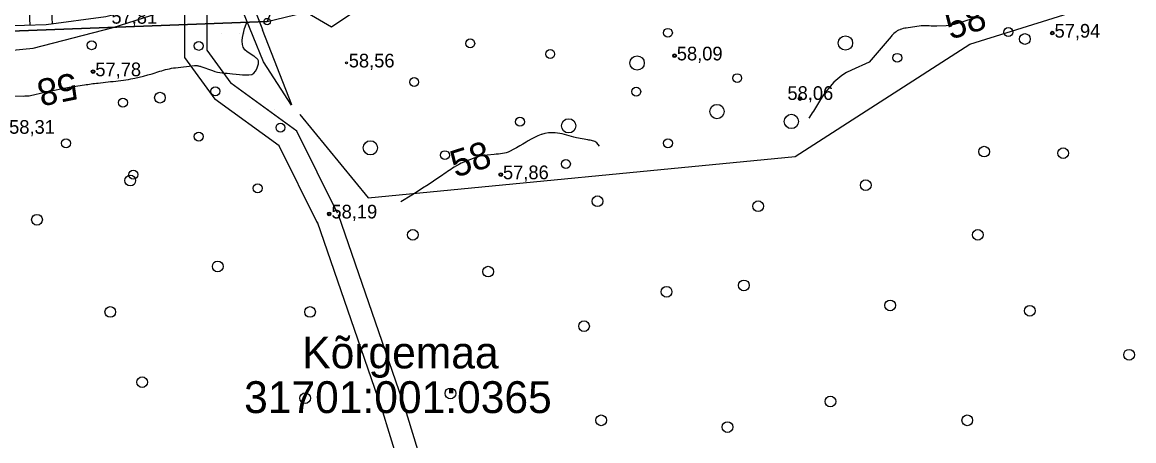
# Model space of a CAD drawing. Extents: x 532503 to 539665, y 6557663 to 6561526.
# Drawn here: x 535060.8 to 535259.9, y 6559424.7 to 6559499.7 of the extents above; entities that cross this region are included whole.
import ezdxf

# ---------------------------------------------------------------- set-up
doc = ezdxf.new("R2010")
doc.units = 0
for name, color, linetype in [('Default', 7, 'Continuous'), ('HALJASTUS', 7, 'Continuous'), ('HORISONTAAL-EH2000', 7, 'Continuous'), ('kataster', 7, 'Continuous'), ('KORGUS-EH2000', 7, 'Continuous'), ('PIIRIMLEITUD', 7, 'Continuous'), ('RELJEEF', 7, 'Continuous'), ('RELJEEF 1', 7, 'Continuous'), ('TEE', 7, 'Continuous'), ('TM_aktiivne', 7, 'Continuous')]:
    doc.layers.add(name, color=color, linetype=linetype)

# ---------------------------------------------------------------- blocks, each defined once
blk = doc.blocks.new('LONOOR')
at = {"layer": 'HALJASTUS'}
blk.add_circle((0, 0), 0.6, dxfattribs=at)
blk = doc.blocks.new('POINT_DISPLAY')
at = {"layer": 'Default'}
blk.add_line((0, 0), (0, 0), dxfattribs=at)

msp = doc.modelspace()

# ---------------------------------------------------------------- linework, layer by layer
at = {"layer": 'HALJASTUS'}
msp.add_lwpolyline([(535110.49, 6559483.15), (535110.49, 6559483.15), (535122.71, 6559468.22), (535199.25, 6559475.6), (535230.51, 6559495.77), (535263.23, 6559506), (535276.96, 6559503.95), (535294.2, 6559495.48)], dxfattribs=at)
for centre, radius in [((535176.42, 6559497.78), 0.8), ((535176.42, 6559497.78), 0.8), ((535237.41, 6559497.91), 0.8), ((535237.41, 6559497.91), 0.8), ((535073.19, 6559495.56), 0.8), ((535073.19, 6559495.56), 0.8), ((535092.38, 6559495.44), 0.8), ((535092.38, 6559495.44), 0.8), ((535141.01, 6559495.88), 0.8), ((535141.01, 6559495.88), 0.8), ((535208.23, 6559495.95), 1.28), ((535155.34, 6559493.98), 0.8), ((535155.34, 6559493.98), 0.8), ((535217.51, 6559493.3), 0.8), ((535217.51, 6559493.3), 0.8), ((535170.91, 6559492.37), 1.28), ((535188.84, 6559489.66), 0.8), ((535188.84, 6559489.66), 0.8), ((535095.36, 6559487.31), 0.8), ((535095.36, 6559487.31), 0.8), ((535130.97, 6559488.96), 0.8), ((535130.97, 6559488.96), 0.8), ((535170.75, 6559487.25), 0.8), ((535170.75, 6559487.25), 0.8), ((535078.79, 6559485.28), 0.8), ((535078.79, 6559485.28), 0.8), ((535185.22, 6559483.68), 1.28), ((535149.93, 6559481.85), 0.8), ((535149.93, 6559481.85), 0.8), ((535158.64, 6559481.12), 1.28), ((535198.55, 6559481.9), 1.28), ((535092.38, 6559479.2), 0.8), ((535092.38, 6559479.2), 0.8), ((535107.02, 6559480.8), 0.8), ((535107.02, 6559480.8), 0.8), ((535068.61, 6559477.99), 0.8), ((535068.61, 6559477.99), 0.8), ((535123.13, 6559477.18), 1.28), ((535176.44, 6559478), 0.8), ((535176.44, 6559478), 0.8), ((535136.48, 6559475.87), 0.8), ((535136.48, 6559475.87), 0.8), ((535158.15, 6559474.29), 0.8), ((535158.15, 6559474.29), 0.8), ((535080.66, 6559472.38), 0.8), ((535102.93, 6559469.93), 0.8), ((535102.93, 6559469.93), 0.8)]:
    msp.add_circle(centre, radius, dxfattribs=at)
at = {"layer": 'HORISONTAAL-EH2000'}
for points in [[(535069.14, 6559488.04), (535071.89, 6559488.45), (535072.19, 6559488.5), (535072.5, 6559488.55), (535072.81, 6559488.59), (535073.11, 6559488.64), (535073.42, 6559488.68), (535073.73, 6559488.72), (535074.04, 6559488.76), (535074.35, 6559488.79), (535076.58, 6559489.03), (535077.04, 6559489.07), (535077.5, 6559489.12), (535077.96, 6559489.18), (535078.42, 6559489.23), (535078.87, 6559489.29), (535079.33, 6559489.35), (535079.78, 6559489.43), (535080.24, 6559489.52), (535080.92, 6559489.66), (535081.71, 6559489.83), (535082.49, 6559490.02), (535083.27, 6559490.23), (535084.04, 6559490.46), (535085.4, 6559490.88), (535085.74, 6559490.98), (535086.09, 6559491.08), (535086.44, 6559491.18), (535086.8, 6559491.27), (535087.15, 6559491.35), (535087.5, 6559491.42), (535087.86, 6559491.48), (535088.22, 6559491.53), (535091.64, 6559491.9), (535091.78, 6559491.91), (535091.93, 6559491.91), (535092.07, 6559491.9), (535092.21, 6559491.88), (535092.36, 6559491.86), (535092.5, 6559491.82), (535092.64, 6559491.78), (535092.77, 6559491.74), (535094.84, 6559491), (535095.27, 6559490.87), (535095.71, 6559490.75), (535096.15, 6559490.68), (535096.6, 6559490.62), (535097.05, 6559490.58), (535097.5, 6559490.54), (535097.95, 6559490.49), (535098.4, 6559490.45), (535099.11, 6559490.37), (535099.68, 6559490.31), (535100.24, 6559490.27), (535100.8, 6559490.25), (535101.37, 6559490.23), (535101.86, 6559490.34), (535102.27, 6559490.54), (535102.57, 6559490.88), (535102.8, 6559491.32), (535103.06, 6559492.25), (535103.09, 6559492.37), (535103.1, 6559492.5), (535103.09, 6559492.63), (535103.07, 6559492.75), (535103.03, 6559492.87), (535102.97, 6559492.98), (535102.9, 6559493.08), (535102.81, 6559493.17), (535102.75, 6559493.22), (535102.62, 6559493.32), (535102.49, 6559493.42), (535102.36, 6559493.52), (535102.22, 6559493.61), (535101.07, 6559494.36), (535100.65, 6559494.75), (535100.34, 6559495.19), (535100.19, 6559495.7), (535100.14, 6559496.27), (535100.15, 6559496.38), (535100.22, 6559496.93), (535100.31, 6559497.49), (535100.44, 6559498.03), (535100.6, 6559498.57), (535101.03, 6559499.82)], [(535231.73, 6559500.52), (535227.73, 6559499.25), (535227.49, 6559499.2), (535226.87, 6559499.11), (535226.26, 6559499.05), (535224.63, 6559498.96), (535224.27, 6559498.95), (535223.92, 6559498.95), (535223.56, 6559498.97), (535223.21, 6559499.01), (535222.85, 6559499.04), (535222.5, 6559499.05), (535222.15, 6559499.04), (535221.79, 6559499), (535219.13, 6559498.64), (535218.85, 6559498.59), (535218.57, 6559498.53), (535218.3, 6559498.45), (535218.03, 6559498.35), (535217.97, 6559498.33), (535217.74, 6559498.23), (535217.52, 6559498.11), (535217.31, 6559497.97), (535217.11, 6559497.82), (535216.93, 6559497.66), (535216.74, 6559497.48), (535216.57, 6559497.3), (535216.4, 6559497.12), (535212.5, 6559492.5), (535209.29, 6559491.1), (535208.43, 6559490.66), (535207.61, 6559490.16), (535206.86, 6559489.56), (535206.15, 6559488.91), (535205.49, 6559488.18), (535204.88, 6559487.43), (535204.31, 6559486.65), (535203.78, 6559485.83), (535202.89, 6559484.37), (535202.69, 6559484.05), (535202.49, 6559483.74), (535202.29, 6559483.43), (535202.09, 6559483.12), (535201.67, 6559482.5)], [(535057.94, 6559486.49), (535060.93, 6559486.46), (535061.2, 6559486.47), (535061.46, 6559486.48), (535061.72, 6559486.5), (535061.98, 6559486.52), (535062.24, 6559486.56), (535062.5, 6559486.6), (535062.75, 6559486.65), (535063.01, 6559486.71), (535065.02, 6559487.2), (535069.14, 6559488.04)], [(535164.17, 6559477.5), (535163.67, 6559478.05), (535163.51, 6559478.19), (535163.34, 6559478.31), (535163.14, 6559478.4), (535162.94, 6559478.46), (535162.72, 6559478.5), (535162.5, 6559478.54), (535162.28, 6559478.58), (535162.06, 6559478.62), (535160.03, 6559479), (535159.6, 6559479.09), (535159.17, 6559479.19), (535158.75, 6559479.31), (535158.33, 6559479.44), (535157.91, 6559479.56), (535157.49, 6559479.67), (535157.06, 6559479.74), (535156.63, 6559479.81), (535156.25, 6559479.85), (535155.62, 6559479.88), (535155.01, 6559479.85), (535154.4, 6559479.74), (535153.8, 6559479.57), (535153.75, 6559479.56), (535153.13, 6559479.32), (535152.53, 6559479.05), (535151.95, 6559478.75), (535151.38, 6559478.42), (535151.04, 6559478.21), (535150.46, 6559477.86), (535149.88, 6559477.52), (535149.29, 6559477.19), (535148.7, 6559476.87), (535148.14, 6559476.58), (535147.82, 6559476.43), (535147.48, 6559476.3), (535147.13, 6559476.21), (535146.78, 6559476.15), (535146.42, 6559476.11), (535146.06, 6559476.07), (535145.69, 6559476.03), (535145.33, 6559476), (535144.06, 6559475.89), (535143.29, 6559475.79), (535142.53, 6559475.65), (535142.41, 6559475.62)], [(535142.41, 6559475.62), (535139.41, 6559474.44), (535139.08, 6559474.26), (535138.55, 6559473.96), (535138.11, 6559473.7), (535137.81, 6559473.51), (535137.51, 6559473.32), (535137.22, 6559473.12), (535136.93, 6559472.92), (535136.64, 6559472.71), (535136.35, 6559472.51), (535136.06, 6559472.31), (535135.77, 6559472.11), (535134.41, 6559471.2), (535133.45, 6559470.57), (535132.49, 6559469.94), (535131.52, 6559469.32), (535130.55, 6559468.71), (535128.61, 6559467.5)]]:
    msp.add_lwpolyline(points, dxfattribs=at)
at = {"layer": 'kataster'}
for points in [[(534957.01, 6559532.73), (534874.65, 6559775.26), (534941.15, 6559817.08), (535181.52, 6559689.04), (535104.64, 6559499.79), (534969.93, 6559494.75)], [(534969.93, 6559494.75), (535104.64, 6559499.79), (535276.49, 6559541.25), (535318.85, 6559280.76), (535338.01, 6559156.08), (535319.42, 6559157.12), (535277.91, 6559164.57), (535224.85, 6559174.15), (535170.96, 6559181.67), (535149.92, 6559184.62), (535125.2, 6559187.34), (535093.5, 6559192.16), (535054.28, 6559206.76)]]:
    msp.add_lwpolyline(points, close=True, dxfattribs=at)
at = {"layer": 'KORGUS-EH2000'}
for centre, radius in [((535245.29, 6559497.73), 0.32), ((535245.29, 6559497.73), 0.2), ((535245.29, 6559497.73), 0.2), ((535177.62, 6559493.67), 0.32), ((535177.62, 6559493.67), 0.2), ((535118.85, 6559492.4), 0.2), ((535118.85, 6559492.4), 0.2), ((535073.45, 6559490.83), 0.32), ((535073.45, 6559490.83), 0.2), ((535200.1, 6559486), 0.32), ((535200.1, 6559486), 0.2), ((535146.48, 6559472.39), 0.32), ((535146.48, 6559472.39), 0.2), ((535146.48, 6559472.39), 0.2), ((535115.75, 6559465.35), 0.32), ((535115.75, 6559465.35), 0.2)]:
    msp.add_circle(centre, radius, dxfattribs=at)
at = {"layer": 'PIIRIMLEITUD'}
msp.add_circle((535104.64, 6559499.79), 0.57, dxfattribs=at)
at = {"layer": 'RELJEEF'}
for p, q in [((535061.73, 6559506.63), (535062.14, 6559499.1)), ((535065.73, 6559506.85), (535066.13, 6559499.33))]:
    msp.add_line(p, q, dxfattribs=at)
for points in [[(535109.02, 6559484.82), (535103.98, 6559492.59), (535100.29, 6559501.64), (535100.5, 6559504.84), (535103.25, 6559507.91), (535105.72, 6559508.12), (535110.74, 6559506.58), (535115.7, 6559504.44), (535119.85, 6559506.31), (535124.94, 6559512.6)], [(535109.02, 6559484.82), (535103.98, 6559492.59), (535100.29, 6559501.64), (535100.5, 6559504.84), (535103.25, 6559507.91), (535105.72, 6559508.12), (535110.74, 6559506.58), (535115.7, 6559504.44), (535119.85, 6559506.31), (535124.94, 6559512.6)], [(535114.09, 6559509.72), (535109.81, 6559508.21), (535101.81, 6559506.5), (535087.91, 6559503.76), (535075.73, 6559500.64), (535065.04, 6559499.19), (535049.48, 6559498.72), (535035.15, 6559499.38), (535025.73, 6559500.28), (535016.96, 6559498.58), (535002.85, 6559496.63)], [(535125.39, 6559505.04), (535116.17, 6559498.77), (535105.71, 6559504.91), (535102.67, 6559501.25), (535103.79, 6559498.35)], [(535125.39, 6559505.04), (535116.17, 6559498.77), (535105.71, 6559504.91), (535102.67, 6559501.25), (535103.79, 6559498.35)], [(535103.76, 6559498.4), (535108.99, 6559484.93)], [(535103.76, 6559498.4), (535108.99, 6559484.93)]]:
    msp.add_lwpolyline(points, dxfattribs=at)
at = {"layer": 'RELJEEF 1'}
for points in [[(535109.02, 6559484.82), (535103.98, 6559492.59), (535100.29, 6559501.64), (535100.5, 6559504.84), (535103.25, 6559507.91), (535105.72, 6559508.12), (535110.74, 6559506.58), (535115.7, 6559504.44), (535119.85, 6559506.31), (535124.94, 6559512.6)], [(535125.39, 6559505.04), (535116.17, 6559498.77), (535105.71, 6559504.91), (535102.67, 6559501.25), (535103.79, 6559498.35)], [(535055.91, 6559494.38), (535062.74, 6559495.05), (535077.04, 6559498.73), (535085.08, 6559501.31), (535095.91, 6559503.08), (535100.29, 6559501.64)], [(535103.76, 6559498.4), (535108.99, 6559484.93)]]:
    msp.add_lwpolyline(points, dxfattribs=at)
at = {"layer": 'TEE'}
for p, q in [((535089.8, 6559503.31), (535089.8, 6559493.34)), ((535093.8, 6559503.72), (535093.8, 6559494.66)), ((535093.8, 6559494.66), (535098.14, 6559488.78)), ((535089.8, 6559493.34), (535095.29, 6559485.9)), ((535109.95, 6559480.19), (535098.14, 6559488.78)), ((535106.8, 6559477.53), (535095.29, 6559485.9)), ((535117.25, 6559465.45), (535109.95, 6559480.19)), ((535113.67, 6559463.67), (535106.8, 6559477.53)), ((535117.35, 6559465.22), (535128.84, 6559431.98)), ((535113.57, 6559463.91), (535125.06, 6559430.67)), ((535125.04, 6559430.73), (535136.7, 6559393.22)), ((535128.86, 6559431.92), (535140.52, 6559394.4))]:
    msp.add_line(p, q, dxfattribs=at)
at = {"layer": 'TM_aktiivne'}
msp.add_lwpolyline([(534874.54, 6559775.58), (534941.07, 6559816.91), (535181.4, 6559689.09), (535104.64, 6559499.79), (534969.93, 6559494.75)], close=True, dxfattribs=at)

# ---------------------------------------------------------------- block references
at = {"layer": 'HALJASTUS', "xscale": 1.6, "yscale": 1.6000000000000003}
for p in [(535240.38, 6559496.67), (535085.43, 6559486.16), (535233.09, 6559476.5), (535247.24, 6559476.22), (535080.11, 6559471.32), (535211.87, 6559470.49), (535163.82, 6559467.61), (535192.59, 6559466.72), (535063.4, 6559464.3), (535130.73, 6559461.6), (535231.95, 6559461.6), (535095.78, 6559455.94), (535144.23, 6559455.01), (535176.19, 6559451.4), (535190.04, 6559452.54), (535076.53, 6559447.79), (535112.32, 6559447.79), (535216.25, 6559448.96), (535241.27, 6559448), (535161.4, 6559445.24), (535259.05, 6559440.12), (535082.24, 6559435.21), (535137.47, 6559433.2), (535111.45, 6559432.35), (535205.54, 6559431.75), (535164.47, 6559428.38), (535187.11, 6559427.17), (535230.06, 6559428.38)]:
    msp.add_blockref('LONOOR', p, dxfattribs=at)
at = {"layer": 'RELJEEF'}
for p in [(535096.37, 6559497.7), (535099.69, 6559497.7), (535100.66, 6559497.7), (535101.62, 6559484.12), (535104.94, 6559484.12), (535105.92, 6559484.12)]:
    msp.add_blockref('POINT_DISPLAY', p, dxfattribs=at)

# ---------------------------------------------------------------- texts
at = {"layer": 'HORISONTAAL-EH2000'}
for rotation, p in [(17.5864, (535227.04, 6559496.51)), (191.43, (535070.11, 6559490.68)), (17.5864, (535138.36, 6559471.81))]:
    msp.add_text('58', height=4.8, rotation=rotation, dxfattribs=at).set_placement(p)
at = {"layer": 'kataster'}
for s, p in [('Kõrgemaa', (535110.93, 6559437.68)), ('31701:001:0365', (535100.51, 6559429.68))]:
    msp.add_text(s, height=5.7, dxfattribs=at).set_placement(p)
at = {"layer": 'KORGUS-EH2000'}
for s, p in [('57,81 ', (535076.73, 6559499.41)), ('57,94 ', (535245.69, 6559496.91)), ('58,56 ', (535119.25, 6559491.58)), ('58,09 ', (535178.02, 6559492.84)), ('57,78 ', (535073.85, 6559490)), ('58,06 ', (535197.84, 6559485.76)), ('58,31 ', (535058.41, 6559479.7)), ('57,86 ', (535146.88, 6559471.56)), ('58,19 ', (535116.15, 6559464.53))]:
    msp.add_text(s, height=2.45, dxfattribs=at).set_placement(p)

doc.saveas('drawing.dxf')
